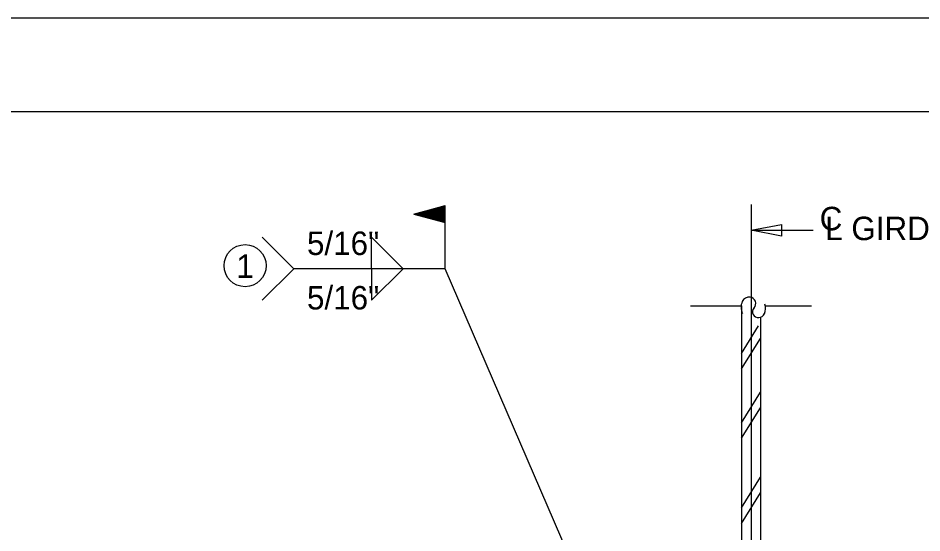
# Model space of a CAD drawing. Extents: x -125.5 to -89.4, y -5.1 to 16.9.
# Drawn here: x -120.383 to -115.571, y 14.192 to 16.934 of the extents above; entities that cross this region are included whole.
import ezdxf

# ---------------------------------------------------------------- set-up
doc = ezdxf.new("R2010")
doc.units = 0
for name, color, linetype in [('BR_AUTO DIMENSION', 7, 'Continuous'), ('BR_BORDER LINES', 7, 'Continuous'), ('BR_CENTER LINES', 7, 'Continuous'), ('BR_STRUCTURAL STEEL', 7, 'Continuous'), ('BR_TEXT', 7, 'Continuous'), ('Level 31', 7, 'Continuous')]:
    doc.layers.add(name, color=color, linetype=linetype)

msp = doc.modelspace()

# ---------------------------------------------------------------- linework, layer by layer
at = {"layer": 'BR_AUTO DIMENSION'}
for p, q in [((-118.2772, 15.8902), (-118.1091, 15.9353)), ((-118.1089, 15.9024), (-118.1349, 15.9284)), ((-118.1089, 15.9055), (-118.1324, 15.929)), ((-118.1089, 15.9087), (-118.1299, 15.9297)), ((-118.1089, 15.9119), (-118.1274, 15.9304)), ((-118.1089, 15.915), (-118.1249, 15.931)), ((-118.1089, 15.9182), (-118.1224, 15.9317)), ((-118.1089, 15.9214), (-118.1199, 15.9324)), ((-118.1089, 15.9246), (-118.1174, 15.933)), ((-118.1089, 15.9277), (-118.1149, 15.9337)), ((-118.1089, 15.9309), (-118.1124, 15.9344)), ((-118.1089, 15.9341), (-118.1099, 15.9351)), ((-118.1091, 15.5991), (-118.1091, 15.9353)), ((-118.2772, 15.8902), (-118.1091, 15.8452)), ((-118.2732, 15.8892), (-118.2749, 15.8909)), ((-118.2689, 15.888), (-118.2724, 15.8915)), ((-118.2646, 15.8869), (-118.2699, 15.8922)), ((-118.2602, 15.8857), (-118.2674, 15.8929)), ((-118.2559, 15.8845), (-118.2649, 15.8935)), ((-118.2516, 15.8834), (-118.2624, 15.8942)), ((-118.2472, 15.8822), (-118.2599, 15.8949)), ((-118.2429, 15.8811), (-118.2574, 15.8955)), ((-118.2386, 15.8799), (-118.2549, 15.8962)), ((-118.2343, 15.8787), (-118.2524, 15.8969)), ((-118.2299, 15.8776), (-118.2499, 15.8975)), ((-118.2256, 15.8764), (-118.2474, 15.8982)), ((-118.2213, 15.8753), (-118.2449, 15.8989)), ((-118.217, 15.8741), (-118.2424, 15.8996)), ((-118.2126, 15.8729), (-118.2399, 15.9002)), ((-118.2083, 15.8718), (-118.2374, 15.9009)), ((-118.204, 15.8706), (-118.2349, 15.9016)), ((-118.1996, 15.8695), (-118.2324, 15.9022)), ((-118.1953, 15.8683), (-118.2299, 15.9029)), ((-118.191, 15.8671), (-118.2274, 15.9036)), ((-118.1866, 15.866), (-118.2249, 15.9042)), ((-118.1823, 15.8648), (-118.2224, 15.9049)), ((-118.178, 15.8637), (-118.2199, 15.9056)), ((-118.1737, 15.8625), (-118.2174, 15.9063)), ((-118.1693, 15.8613), (-118.2149, 15.9069)), ((-118.165, 15.8602), (-118.2124, 15.9076)), ((-118.1607, 15.859), (-118.2099, 15.9083)), ((-118.1563, 15.8579), (-118.2074, 15.9089)), ((-118.152, 15.8567), (-118.2049, 15.9096)), ((-118.1477, 15.8555), (-118.2024, 15.9103)), ((-118.1433, 15.8544), (-118.1999, 15.9109)), ((-118.139, 15.8532), (-118.1974, 15.9116)), ((-118.1347, 15.8521), (-118.1949, 15.9123)), ((-118.1304, 15.8509), (-118.1924, 15.913)), ((-118.126, 15.8497), (-118.1899, 15.9136)), ((-118.1217, 15.8486), (-118.1874, 15.9143)), ((-118.1174, 15.8474), (-118.1849, 15.915)), ((-118.113, 15.8463), (-118.1824, 15.9156)), ((-118.1091, 15.8455), (-118.1799, 15.9163)), ((-118.1089, 15.8485), (-118.1774, 15.917)), ((-118.1089, 15.8517), (-118.1749, 15.9176)), ((-118.1089, 15.8548), (-118.1724, 15.9183)), ((-118.1089, 15.858), (-118.1699, 15.919)), ((-118.1089, 15.8612), (-118.1674, 15.9197)), ((-118.1089, 15.8643), (-118.1649, 15.9203)), ((-118.1089, 15.8675), (-118.1624, 15.921)), ((-118.1089, 15.8707), (-118.1599, 15.9217)), ((-118.1089, 15.8739), (-118.1574, 15.9223)), ((-118.1089, 15.877), (-118.1549, 15.923)), ((-118.1089, 15.8802), (-118.1524, 15.9237)), ((-118.1089, 15.8834), (-118.1499, 15.9243)), ((-118.1089, 15.8865), (-118.1474, 15.925)), ((-118.1089, 15.8897), (-118.1449, 15.9257)), ((-118.1089, 15.8929), (-118.1424, 15.9263)), ((-118.1089, 15.896), (-118.1399, 15.927)), ((-118.1089, 15.8992), (-118.1374, 15.9277)), ((-116.4811, 15.8038), (-116.1506, 15.8038)), ((-119.0832, 15.7672), (-118.9151, 15.5991)), ((-118.5013, 15.5991), (-118.5013, 15.7672)), ((-118.3332, 15.5991), (-118.5013, 15.7672)), ((-118.9151, 15.5991), (-119.0832, 15.431)), ((-118.1091, 15.5991), (-118.9151, 15.5991)), ((-118.3332, 15.5991), (-118.5013, 15.431)), ((-118.5013, 15.5991), (-118.5013, 15.431)), ((-117.1478, 13.3682), (-118.1091, 15.5991))]:
    msp.add_line(p, q, dxfattribs=at)
msp.add_lwpolyline([(-116.3186, 15.7725), (-116.4811, 15.8038), (-116.3186, 15.835)], close=True, dxfattribs=at)
msp.add_circle((-119.1748, 15.6153), 0.1121, dxfattribs=at)
at = {"layer": 'BR_BORDER LINES'}
msp.add_line((-90.0334, 16.4338), (-123.6994, 16.4338), dxfattribs=at)
at = {"layer": 'BR_CENTER LINES'}
msp.add_line((-116.4811, 15.9412), (-116.4811, 12.8489), dxfattribs=at)
at = {"layer": 'BR_STRUCTURAL STEEL'}
for p, q in [((-116.5311, 15.4006), (-116.5311, 13.4682)), ((-116.4311, 15.3403), (-116.4311, 13.4682)), ((-116.5311, 15.1479), (-116.4406, 15.2955)), ((-116.5311, 15.0651), (-116.4311, 15.2282)), ((-116.5311, 14.7786), (-116.4311, 14.9416)), ((-116.5311, 14.6958), (-116.4311, 14.8589)), ((-116.5311, 14.3256), (-116.4311, 14.4887)), ((-116.5311, 14.2428), (-116.4311, 14.4059))]:
    msp.add_line(p, q, dxfattribs=at)
at = {"layer": 'BR_TEXT'}
for p, q in [((-116.8038, 15.4016), (-116.534, 15.4016)), ((-116.4049, 15.4016), (-116.1587, 15.4016))]:
    msp.add_line(p, q, dxfattribs=at)
for centre, radius, start, end in [((-116.491, 15.4071), 0.0406, 83.2422, 155.6187), ((-116.4902, 15.4137), 0.034, 316.8236, 83.2422), ((-116.4626, 15.3943), 0.0718, 155.6187, 208.3414), ((-116.475, 15.389), 0.0713, 335.6333, 17.6449), ((-116.4428, 15.3692), 0.031, 136.8236, 275.5224), ((-116.4434, 15.3747), 0.0365, 275.5224, 335.6333)]:
    msp.add_arc(centre, radius, start, end, dxfattribs=at)
at = {"layer": 'Level 31'}
msp.add_lwpolyline([(-125.5328, -5.0661), (-89.5328, -5.0661), (-89.5328, 16.9339), (-125.5328, 16.9339)], close=True, dxfattribs=at)

# ---------------------------------------------------------------- texts
at = {"layer": 'BR_AUTO DIMENSION'}
for s, p in [('C', (-116.1158, 15.8037)), ('L GIRDER', (-116.0864, 15.7511)), ('1', (-119.2216, 15.5503))]:
    msp.add_text(s, height=0.125, dxfattribs=at).set_placement(p)
at = {"layer": 'BR_TEXT'}
for p in [(-118.8454, 15.672), (-118.8454, 15.382)]:
    msp.add_text('5/16"', height=0.125, dxfattribs=at).set_placement(p)

doc.saveas('drawing.dxf')
